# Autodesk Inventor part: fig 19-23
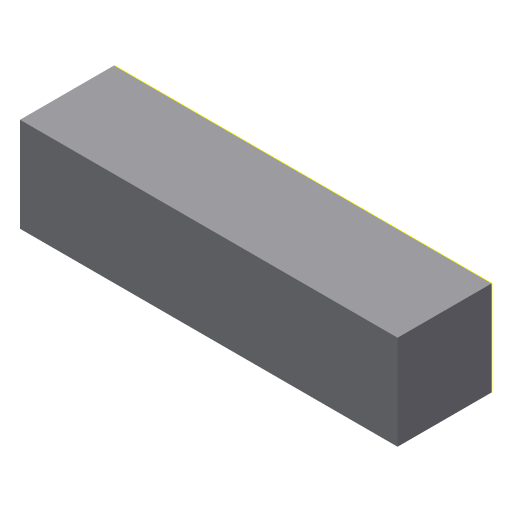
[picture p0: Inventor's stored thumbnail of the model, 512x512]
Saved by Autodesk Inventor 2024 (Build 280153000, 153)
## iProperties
Created: 2013-07
Part Number: fig 19-23
Material: Generic
Document SubType Name: Modeling
Designer: CADCIM
Density: 1 g/cm^3
Appearance: Default
Author: CADCIM
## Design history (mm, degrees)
sketch "Sketch1"
  geometry: L1 (-20, 5)-(20, 5); L2 (20, 5)-(20, -5); L3 (20, -5)-(-20, -5); L4 (-20, -5)-(-20, 5); L5 (-20, 5)-(20, -5); L6 (20, 5)-(-20, -5); 1 further point
  constraints: 12 end point, 2 midpoint, 2 parallel, 1 horizontal, 1 perpendicular
  dimensions: "d0" = 40 distance of L2.end L3.end; "d1" = 10 distance of L1.end L2.end
extrude "Extrusion1" new body sketch "Sketch1" distance "d2" = 10; taper "d3" = 0 deg
sketch "Sketch2"
  geometry: L1 (0, 0)-(40, 0) reference; L2 (0, 0)-(0, -10) reference; L3 (40, -10)-(0, -10) reference; L4 (40, 0)-(40, -10) reference; 2 further points
body "Solid1"
